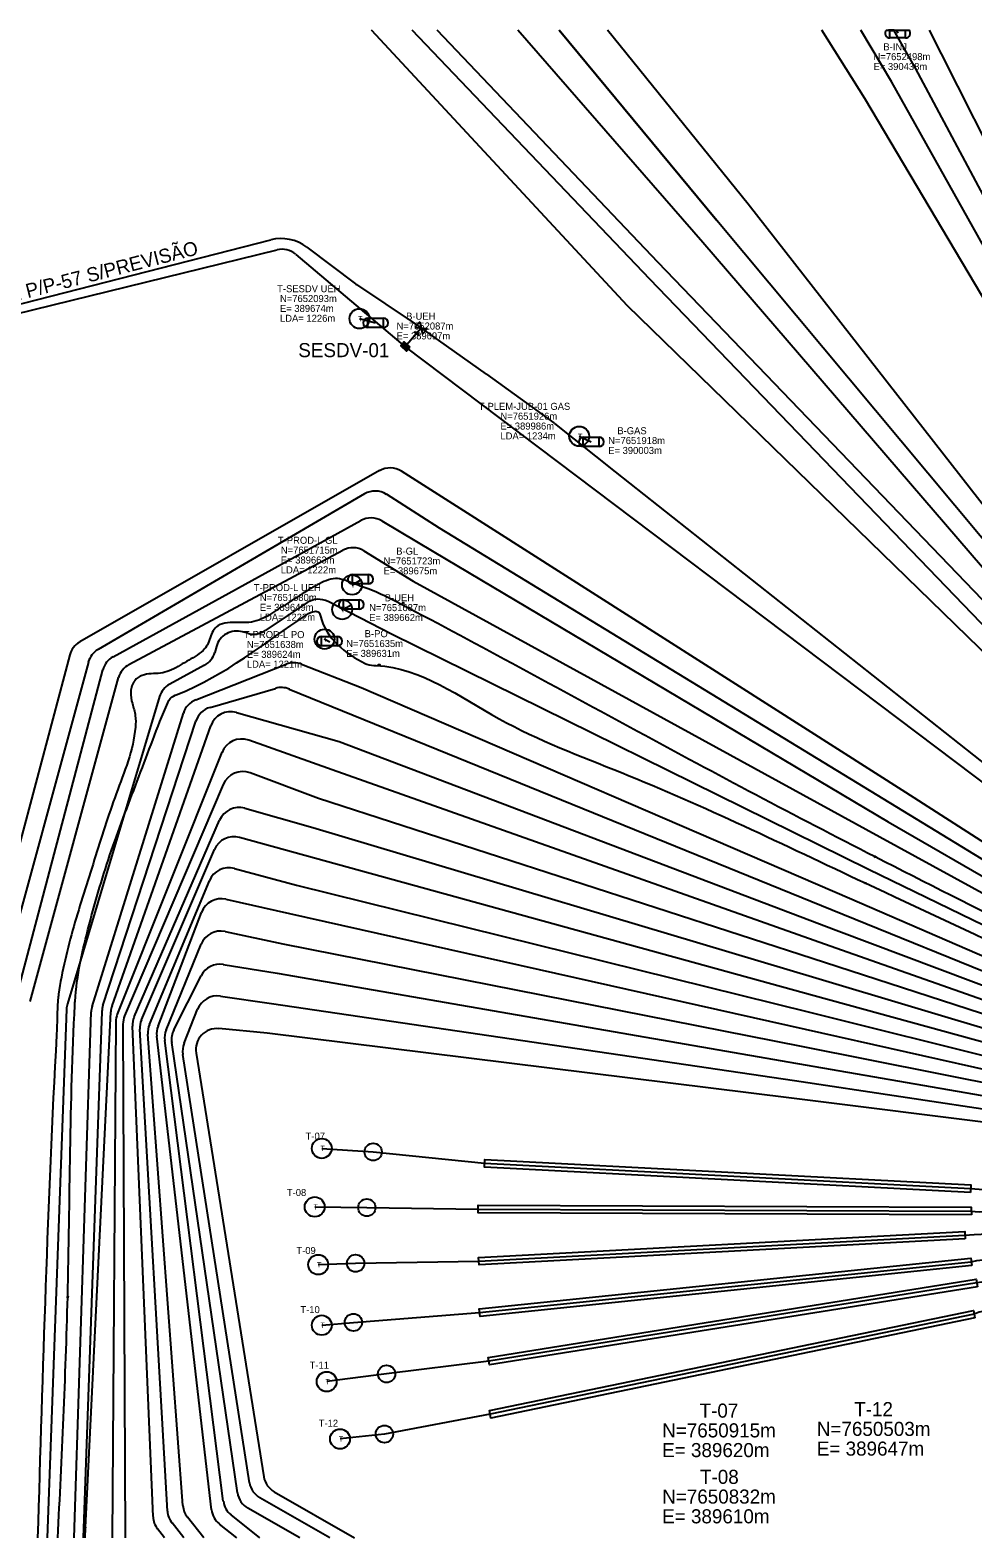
# Model space of a CAD drawing. Extents: x 387828 to 391861, y 7650362 to 7652502.
# Drawn here: x 389207 to 390545, y 7650362 to 7652502 of the extents above; entities that cross this region are included whole.
import ezdxf

# ---------------------------------------------------------------- set-up
doc = ezdxf.new("R2010")
doc.units = 0
for name, color, linetype in [('Blocos de producao br', 7, 'Continuous'), ('Coral', 7, 'Continuous'), ('Plataforma movel NS', 7, 'Continuous'), ('Sistemas de ancoragem', 7, 'Continuous'), ('TDP', 7, 'Continuous'), ('Textos dos campos', 7, 'Continuous'), ('Textos dos sistemas de ancoragem', 7, 'Continuous'), ('Variacoes de flexivel', 7, 'Continuous')]:
    doc.layers.add(name, color=color, linetype=linetype)

msp = doc.modelspace()

# ---------------------------------------------------------------- linework, layer by layer
at = {"layer": 'Blocos de producao br'}
for points in [[(389736.6, 7651688.6), (389735, 7651689.4), (389735.4, 7651690.2), (389737, 7651689.4)], [(389701.1, 7651602.5), (389702.9, 7651602.2), (389702.8, 7651601.3), (389701, 7651601.6)], [(390406.6, 7651328.2), (390405, 7651329), (390405.4, 7651329.8), (390407, 7651329)], [(390391.1, 7651292.8), (390392.8, 7651292), (390392.4, 7651291.2), (390390.8, 7651291.9)], [(389259.4, 7650703.1), (389259.5, 7650704.9), (389260.4, 7650704.9), (389260.3, 7650703)]]:
    msp.add_lwpolyline(points, close=True, dxfattribs=at)
at = {"layer": 'Plataforma movel NS'}
for points in [[(390838, 7651111), (390406, 7651329), (390236.7, 7651416.8), (390068.9, 7651507), (389901.1, 7651597.9), (389732, 7651688), (389686.6, 7651709.3), (389663.4, 7651717.7), (389640, 7651724), (389627, 7651721), (389601.8, 7651708.1), (389578.2, 7651693.1), (389554.9, 7651678), (389531, 7651665), (389517, 7651661.8), (389501.8, 7651661.8), (389486.7, 7651661.4), (389473, 7651657), (389466.3, 7651649.8), (389462.2, 7651640), (389458.2, 7651630), (389452, 7651622), (389428.6, 7651606.4), (389404, 7651593), (389391.7, 7651589.8), (389378.3, 7651588.9), (389365.6, 7651586.6), (389359.9, 7651583.7), (389355, 7651579), (389349.4, 7651563.3), (389351.7, 7651546.5), (389355.9, 7651529.5), (389356, 7651513), (389328.8, 7651418.6), (389297.7, 7651324.7), (389268.5, 7651230.2), (389247, 7651134), (389246, 7651126), (389245, 7651099), (389244, 7651076), (389217.2, 7650362.3)], [(389245.9, 7650362.3), (389259.9, 7650704), (389270, 7651118.4), (389270.3, 7651123.7), (389290.3, 7651232.4), (389322.1, 7651338.3), (389361, 7651442.8), (389401.9, 7651547.4), (389405.4, 7651553.7), (389415.3, 7651559.4), (389599.1, 7651672.6), (389610.3, 7651677.5), (389616.5, 7651676.1), (389618.8, 7651670.6), (389682, 7651603.6), (389684.6, 7651602.4), (389697.9, 7651600.5), (389872.2, 7651525.1), (390045.9, 7651448.6), (390391.8, 7651292), (390844.6, 7651082.5)]]:
    msp.add_spline(points, degree=3, dxfattribs=at)
at = {"layer": 'Sistemas de ancoragem'}
for p, q in [((390433.2, 7652502.5), (390424.8, 7652502.5)), ((390435.8, 7652502.5), (390438, 7652498)), ((389674, 7652093), (389697, 7652087)), ((389986, 7651926), (390003, 7651918)), ((389663.9, 7651714.8), (389676.2, 7651722.4)), ((389649.1, 7651679), (389662.2, 7651686.7)), ((389623.8, 7651638.6), (389632.2, 7651634.4))]:
    msp.add_line(p, q, dxfattribs=at)
for points in [[(389620.5, 7650915.1), (389693.5, 7650910.1), (389851.5, 7650894.1), (390541.5, 7650858.1), (390553.5, 7650857.1), (391048.5, 7650835.1), (391164.5, 7650832.6)], [(389610.5, 7650832.1), (389684.5, 7650831.1), (389842.5, 7650829.1), (390542.5, 7650826.1), (390553.5, 7650825.1), (391050.5, 7650827.1), (391164, 7650829.8)], [(389615.5, 7650750.1), (389668.5, 7650752.1), (389843.5, 7650755.1), (390533.5, 7650792.1), (390546.5, 7650793.1), (391044.5, 7650817.1), (391163.4, 7650827)], [(389620.5, 7650664.1), (389665.5, 7650668.1), (389844.5, 7650682.1), (390542.5, 7650754.1), (390550.5, 7650756.1), (391045.5, 7650809.1), (391162.9, 7650824.3)], [(391162.4, 7650821.5), (391054.5, 7650799.1), (390557.5, 7650725.1), (390550.5, 7650724.1), (389857.5, 7650613.1), (389712.5, 7650595.1), (389627.5, 7650584.1)], [(391157.8, 7650817.3), (391046.5, 7650788.7), (390553.5, 7650682.7), (390546.5, 7650679.7), (389859.5, 7650537.7), (389709.5, 7650509.7), (389646.5, 7650502.7)]]:
    msp.add_lwpolyline(points, dxfattribs=at)
for points in [[(390541.3, 7650852.7), (389851.3, 7650888.7), (389851.8, 7650899.5), (390541.8, 7650863.5)], [(390542.6, 7650820.7), (389842.6, 7650823.7), (389842.5, 7650834.5), (390542.5, 7650831.5)], [(390533.9, 7650786.7), (389843.9, 7650749.7), (389843.2, 7650760.4), (390533.2, 7650797.4)], [(390543.2, 7650748.7), (389845.2, 7650676.7), (389843.9, 7650687.4), (390541.9, 7650759.4)], [(390551.5, 7650718.8), (389858.5, 7650607.8), (389856.6, 7650618.4), (390549.6, 7650729.4)], [(390547.7, 7650674.4), (389860.7, 7650532.4), (389858.4, 7650542.9), (390545.4, 7650684.9)]]:
    msp.add_lwpolyline(points, close=True, dxfattribs=at)
for centre in [(389674, 7652093), (389986, 7651926), (389663.5, 7651715.1), (389649.5, 7651680.1), (389624.5, 7651638.1), (389620.5, 7650915.1), (389610.5, 7650832.1), (389615.5, 7650750.1), (389620.5, 7650664.1), (389627.5, 7650584.1), (389646.5, 7650502.7)]:
    msp.add_circle(centre, 14.1, dxfattribs=at)
msp.add_arc((390429, 7652516), 14.1, 252.6797, 287.3203, dxfattribs=at)
at = {"layer": 'TDP'}
for centre in [(389693.5, 7650910.1), (389684.5, 7650831.1), (389668.5, 7650752.1), (389665.5, 7650668.1), (389712.5, 7650595.1), (389709.5, 7650509.7)]:
    msp.add_circle(centre, 12.3, dxfattribs=at)
at = {"layer": 'Textos dos campos'}
for p, q in [((390421.9, 7652502.5), (390454.1, 7652502.5)), ((390426.8, 7652491.4), (390426.8, 7652502.5)), ((390449.3, 7652491.4), (390449.3, 7652502.5)), ((390449.3, 7652491.4), (390426.8, 7652491.4)), ((389685.8, 7652080.4), (389685.8, 7652093.6)), ((389708.3, 7652080.4), (389708.3, 7652093.6)), ((389708.3, 7652080.4), (389685.8, 7652080.4)), ((389991.8, 7651911.4), (389991.8, 7651924.6)), ((390014.3, 7651911.4), (390014.3, 7651924.6)), ((390014.3, 7651911.4), (389991.8, 7651911.4)), ((389664.3, 7651716.5), (389664.3, 7651729.7)), ((389686.8, 7651716.5), (389686.8, 7651729.7)), ((389686.8, 7651716.5), (389664.3, 7651716.5)), ((389651.3, 7651680.5), (389651.3, 7651693.7)), ((389673.8, 7651680.5), (389651.3, 7651680.5)), ((389673.8, 7651680.5), (389673.8, 7651693.7)), ((389620.3, 7651628.5), (389620.3, 7651641.7)), ((389642.8, 7651628.5), (389642.8, 7651641.7)), ((389642.8, 7651628.5), (389620.3, 7651628.5))]:
    msp.add_line(p, q, dxfattribs=at)
for points in [[(389685.8, 7652093.6), (389697, 7652093.6), (389708.3, 7652093.6)], [(389991.8, 7651924.6), (390003, 7651924.6), (390014.3, 7651924.6)], [(389664.3, 7651729.7), (389675.6, 7651729.7), (389686.8, 7651729.7)], [(389651.3, 7651693.7), (389662.6, 7651693.7), (389673.8, 7651693.7)], [(389620.3, 7651641.7), (389631.6, 7651641.7), (389642.8, 7651641.7)]]:
    msp.add_lwpolyline(points, dxfattribs=at)
for centre, radius, start, end in [((390426.8, 7652498), 6.6, 137.0647, 270.0255), ((390449.3, 7652498), 6.59, 270.0255, 43.0162), ((389685.8, 7652087), 6.6, 90, 270), ((389708.3, 7652087), 6.59, 270, 90), ((389991.8, 7651918), 6.6, 90, 270), ((390014.3, 7651918), 6.59, 270, 90), ((389664.3, 7651723.1), 6.6, 90, 270), ((389686.8, 7651723.1), 6.59, 270, 90), ((389651.3, 7651687.1), 6.6, 90, 270), ((389673.8, 7651687.1), 6.59, 270, 90), ((389620.3, 7651635.1), 6.6, 90, 270), ((389642.8, 7651635.1), 6.59, 270, 90)]:
    msp.add_arc(centre, radius, start, end, dxfattribs=at)
at = {"layer": 'Variacoes de flexivel'}
for p, q in [((390054.5, 7652111.3), (389691.1, 7652502.5)), ((390086.3, 7652149), (389748.7, 7652502.5)), ((390097.8, 7652172.9), (389784.4, 7652502.5)), ((390161.5, 7652201.2), (389898.7, 7652502.5)), ((389957.3, 7652502.5), (390181.2, 7652232.1)), ((390181.2, 7652232.1), (389957.3, 7652502.5)), ((390225.9, 7652255.7), (390026, 7652502.5)), ((390391.5, 7652405.6), (390330.2, 7652502.5)), ((390429.8, 7652428.9), (390385.7, 7652502.5)), ((390463.2, 7652448.4), (390432.6, 7652502.5)), ((390500.1, 7652468.8), (390483.1, 7652502.5)), ((390842.7, 7651790.4), (390500.1, 7652468.8)), ((390800.4, 7651765.4), (390429.8, 7652428.9)), ((390821.2, 7651778), (390463.2, 7652448.4)), ((390779, 7651751.8), (390391.5, 7652405.6)), ((390681.5, 7651671.6), (390225.9, 7652255.7)), ((390662.1, 7651656.5), (390181.2, 7652232.1)), ((388291.9, 7651884.1), (389548.2, 7652204.7)), ((389599.2, 7652194.5), (389668.2, 7652142.3)), ((390643.1, 7651641), (390161.5, 7652201.2)), ((388291.8, 7651879.6), (389557, 7652190.5)), ((389583.6, 7652184.2), (389738.7, 7652052.9)), ((390624.5, 7651625), (390097.8, 7652172.9)), ((389669.7, 7652141.3), (389751.9, 7652086.4)), ((390606.3, 7651608.6), (390086.3, 7652149)), ((390588.7, 7651591.7), (390054.5, 7652111.3)), ((389751.9, 7652086.4), (389853.9, 7652014.2)), ((389759.5, 7652088.4), (389752.5, 7652080.4)), ((389759.5, 7652088.4), (389763.5, 7652070.8)), ((389754.6, 7652071.5), (389738.9, 7652052.9)), ((389752.5, 7652080.4), (389770.5, 7652078.8)), ((389761.5, 7652079.6), (389755.7, 7652072.6)), ((389763.5, 7652070.8), (389770.5, 7652078.8)), ((389732.7, 7652054.4), (389735.1, 7652054.5)), ((389737.7, 7652059.9), (389737.8, 7652057.4)), ((389738.7, 7652052.9), (390572.9, 7651423.5)), ((389740.9, 7652049.3), (389741, 7652046.9)), ((389743.6, 7652052.2), (389746, 7652052.3)), ((389854.2, 7652014), (389950, 7651944.9)), ((389951.1, 7651944), (390037.2, 7651875.5)), ((389702.6, 7651877.2), (389276.9, 7651634)), ((389816.8, 7651823.5), (389733.6, 7651876.4)), ((390037.2, 7651875.5), (390586.1, 7651441.1)), ((389681.1, 7651844.2), (389303, 7651623.3)), ((389787.8, 7651795.4), (389712.4, 7651843.6)), ((390449.5, 7651420.4), (389816.8, 7651823.5)), ((389324.3, 7651613.1), (389676, 7651806.4)), ((389705.8, 7651805.9), (389779.7, 7651762)), ((390436.7, 7651399.7), (389787.8, 7651795.4)), ((389346.8, 7651602), (389650.5, 7651764.2)), ((389680.4, 7651763.3), (389750.3, 7651720.2)), ((389779.7, 7651762), (390424.4, 7651378.8)), ((389750.3, 7651720.2), (390412.5, 7651357.6)), ((389599.2, 7651689.6), (389540.1, 7651650.3)), ((389719.6, 7651645), (389629.6, 7651691.3)), ((389515.4, 7651646.3), (389508, 7651648.4)), ((390396.8, 7651311.1), (389719.6, 7651645)), ((389262.8, 7651615.6), (388929.3, 7650362.3)), ((389471, 7651627.6), (389468.7, 7651619.2)), ((389289.2, 7651605.3), (388950.3, 7650362.3)), ((389187, 7651130.1), (389309.8, 7651594.4)), ((389454.1, 7651600.9), (389404.7, 7651574.1)), ((389441.8, 7651551.9), (389570, 7651602.5)), ((389592, 7651602.6), (389676.3, 7651569.6)), ((389206.6, 7651123.8), (389332, 7651583.4)), ((389390.3, 7651556.4), (389259.5, 7651120.4)), ((389461.9, 7651541.1), (389554.8, 7651568.2)), ((389574.5, 7651567.2), (389665.2, 7651530.3)), ((389676.3, 7651569.6), (390369.4, 7651270.2)), ((389294.7, 7651116.8), (389424.2, 7651532.9)), ((389499.3, 7651533.9), (389645, 7651492.9)), ((389665.2, 7651530.3), (390360, 7651247.7)), ((389310, 7651117.9), (389441.8, 7651521.6)), ((389322.8, 7651117.6), (389462.9, 7651515)), ((389635.3, 7651452.5), (389516.8, 7651494.5)), ((389645, 7651492.9), (390350.9, 7651225.1)), ((389478.9, 7651477.4), (389330.3, 7651105.9)), ((389616, 7651412), (389518.7, 7651448.1)), ((390342.3, 7651202.2), (389635.3, 7651452.5)), ((389480.7, 7651431.7), (389340.7, 7651103.4)), ((390334.2, 7651179), (389616, 7651412)), ((391263.3, 7650896.9), (390449.5, 7651420.4)), ((389354.2, 7651101.7), (389475.6, 7651381)), ((389511.2, 7651397.9), (389608, 7651370.7)), ((391262.4, 7650895.3), (390436.7, 7651399.7)), ((389608, 7651370.7), (390326.5, 7651155.7)), ((390424.4, 7651378.8), (391261.6, 7650893.7)), ((389364.7, 7651097.8), (389468.3, 7651339.6)), ((389503.8, 7651356.7), (389596.3, 7651331.2)), ((390412.5, 7651357.6), (391260.8, 7650892.1)), ((389596.3, 7651331.2), (390319.4, 7651132.1)), ((389375.9, 7651091), (389461.1, 7651295)), ((389496.6, 7651312.4), (389584.8, 7651288.6)), ((391259.9, 7650890.5), (390396.8, 7651311.1)), ((389584.8, 7651288.6), (390312.8, 7651108.3)), ((389484.6, 7651268.7), (389574.8, 7651248.5)), ((390369.4, 7651270.2), (391257.4, 7650885.7)), ((389388.1, 7651088.6), (389450, 7651250.2)), ((389574.8, 7651248.5), (390306.6, 7651084.4)), ((390360, 7651247.7), (391256.5, 7650884.1)), ((389483.3, 7651223.1), (389565.3, 7651205.5)), ((390350.9, 7651225.1), (391255.7, 7650882.5)), ((389399.6, 7651083.2), (389449.2, 7651205)), ((389565.3, 7651205.5), (390301, 7651060.2)), ((391254.8, 7650880.9), (390342.3, 7651202.2)), ((389480.8, 7651176.4), (389557, 7651164.1)), ((391253.9, 7650879.3), (390334.2, 7651179)), ((389410.5, 7651083.3), (389449.3, 7651160.2)), ((389557, 7651164.1), (390296, 7651035.8)), ((390326.5, 7651155.7), (391253.1, 7650877.7)), ((389476.6, 7651131.3), (389549.4, 7651120.6)), ((390319.4, 7651132.1), (391252.3, 7650876.1)), ((389269.2, 7650362.3), (389293.3, 7651108.8)), ((389282.3, 7650362.3), (389308.6, 7651109.6)), ((389285.3, 7650377.2), (389321.1, 7651109.1)), ((389425.1, 7651064.3), (389444.3, 7651112.7)), ((389549.4, 7651120.6), (390291.4, 7651011.3)), ((390312.8, 7651108.3), (391251.4, 7650874.5)), ((389328.2, 7651095), (389322.8, 7650362.3)), ((389338.3, 7651091.5), (389341.6, 7650362.3)), ((389381, 7650392.4), (389351.7, 7651088.5)), ((389401.6, 7650400.3), (389362.3, 7651084.3)), ((389543.1, 7651078.8), (389474.4, 7651085.1)), ((390306.6, 7651084.4), (391250.6, 7650872.9)), ((389423.3, 7650408.1), (389373.7, 7651077.2)), ((389464.1, 7650402), (389386.3, 7651074.4)), ((389480.8, 7650414.6), (389397.6, 7651068.1)), ((389501, 7650426), (389407.6, 7651065.5)), ((390287.4, 7650986.5), (389543.1, 7651078.8)), ((390301, 7651060.2), (391249.7, 7650871.3)), ((389518, 7650440.6), (389423.3, 7651048.6)), ((389442.1, 7651050.4), (389538.3, 7650449.1)), ((390296, 7651035.8), (391248.9, 7650869.8)), ((390291.4, 7651011.3), (391248, 7650868.2)), ((391247.2, 7650866.5), (390287.4, 7650986.5)), ((389632.1, 7650362.3), (389532.7, 7650419.2)), ((389553, 7650427.8), (389667, 7650362.3)), ((389532.7, 7650362.3), (389491.8, 7650394.9)), ((389589.3, 7650362.3), (389515.8, 7650404.3)), ((389284.8, 7650362.3), (389285.2, 7650376.7)), ((389397.4, 7650362.3), (389387.4, 7650375.1)), ((389424.7, 7650362.3), (389408, 7650383.4)), ((389453.1, 7650362.3), (389429.8, 7650391.6)), ((389500.1, 7650362.3), (389475.3, 7650381.9))]:
    msp.add_line(p, q, dxfattribs=at)
for points in [[(389753, 7652074.9), (389758.4, 7652070.3), (389757.5, 7652069.2), (389752, 7652073.8)], [(389746, 7652052.3), (389737.7, 7652059.9), (389732.7, 7652054.4), (389741, 7652046.9)], [(389743.6, 7652052.2), (389737.8, 7652057.4), (389735.1, 7652054.5), (389740.9, 7652049.3)]]:
    msp.add_lwpolyline(points, close=True, dxfattribs=at)
msp.add_lwpolyline([(389258.2, 7651112.9), (389230.6, 7650362.3)], dxfattribs=at)
for centre, radius, start, end in [((389563, 7652146.6), 60, 52.9303, 104.3183), ((389564.2, 7652161.4), 30, 49.7436, 103.8037), ((389686.3, 7652166.2), 30, 232.9303, 236.2803), ((389836.6, 7651989.7), 30, 54.183, 54.7117), ((389932.4, 7651920.5), 30, 51.4597, 54.183), ((389717.5, 7651851.1), 30, 57.5025, 119.7371), ((389696.2, 7651818.3), 30, 57.465, 120.2923), ((389690.4, 7651780.1), 30, 59.2751, 118.8023), ((389664.7, 7651737.8), 30, 58.3166, 118.111), ((389615.8, 7651664.6), 30, 62.7809, 123.6471), ((389499.9, 7651619.5), 30, 74.4018, 164.4018), ((389523.5, 7651675.2), 30, 254.4018, 303.6471), ((389291.8, 7651607.9), 30, 119.7371, 165.1023), ((389318.1, 7651597.4), 30, 120.2923, 164.7508), ((389439.8, 7651627.2), 30, 298.4385, 344.4018), ((389338.8, 7651586.8), 30, 118.8023, 165.1912), ((389361, 7651575.5), 30, 118.111, 164.7379), ((389581, 7651574.6), 30, 68.6631, 111.5428), ((389419, 7651547.8), 30, 118.4385, 163.3004), ((389452.8, 7651524), 30, 111.5428, 162.7145), ((389563.2, 7651539.4), 30, 67.8648, 106.2579), ((389470.3, 7651512.3), 30, 106.2579, 161.9266), ((389491.2, 7651505), 30, 74.2651, 160.5813), ((389506.8, 7651466.2), 30, 70.4881, 158.1989), ((389508.3, 7651420), 30, 69.6581, 156.9077), ((389503.1, 7651369), 30, 74.3336, 156.5098), ((389495.8, 7651327.7), 30, 74.5986, 156.8022), ((389488.8, 7651283.5), 30, 74.8541, 157.336), ((389478, 7651239.5), 30, 77.3542, 159.0305), ((389477, 7651193.7), 30, 77.9229, 157.8338), ((389476.1, 7651146.7), 30, 80.8652, 153.2689), ((389472.2, 7651101.6), 30, 81.6289, 158.3207), ((389288.2, 7651111.8), 30, 163.3004, 177.8886), ((389323.3, 7651107.9), 30, 162.7145, 178.1509), ((389338.5, 7651108.6), 30, 161.9266, 177.9894), ((389351.1, 7651107.6), 30, 160.5813, 177.1959), ((389358.2, 7651094.7), 30, 158.1989, 179.5817), ((389368.3, 7651091.6), 30, 156.9077, 180.2569), ((389381.7, 7651089.7), 30, 156.5098, 182.4067), ((389392.2, 7651086), 30, 156.8022, 183.2883), ((389403.6, 7651079.5), 30, 157.336, 184.2447), ((389416.1, 7651077.9), 30, 159.0305, 186.6042), ((389427.4, 7651071.9), 30, 157.8338, 187.2551), ((389437.3, 7651069.8), 30, 153.2689, 188.303), ((389471.7, 7651055.2), 30, 84.7597, 189.094), ((389453, 7651053.2), 30, 158.3207, 188.8471), ((389547.6, 7650445.2), 30, 188.8471, 240.2219), ((389567.9, 7650453.8), 30, 189.094, 240.131), ((389530.6, 7650430.4), 30, 188.303, 240.2636), ((389431.5, 7650402), 30, 183.2883, 218.3784), ((389453.3, 7650410.3), 30, 184.2447, 218.5182), ((389493.9, 7650405.5), 30, 186.6042, 231.6484), ((389510.6, 7650418.4), 30, 187.2551, 231.3908), ((389315.2, 7650375.8), 30, 177.1959, 178.2334), ((389411, 7650393.6), 30, 182.4067, 218.153)]:
    msp.add_arc(centre, radius, start, end, dxfattribs=at)

# ---------------------------------------------------------------- texts
at = {"layer": 'Coral'}
msp.add_text('PROJETO DO GASOD.9.13"/UH DO PLEM-JUB-01 P/P-57 S/PREVISÃO', height=20, rotation=14.3587, dxfattribs=at).set_placement((388596.5, 7651966.8))
msp.add_text('SESDV-01', height=20, dxfattribs=at).set_placement((389587.2, 7652038.3))
at = {"layer": 'Sistemas de ancoragem'}
for p in [(389672.1, 7652089.2), (389984.1, 7651922.2), (389661.6, 7651711.3), (389647.6, 7651676.3), (389622.6, 7651634.3), (389618.6, 7650911.3), (389608.6, 7650828.3), (389613.6, 7650746.3), (389618.6, 7650660.3), (389625.6, 7650580.3), (389644.6, 7650498.9)]:
    msp.add_text('T', height=7.62, dxfattribs=at).set_placement(p)
at = {"layer": 'Textos dos sistemas de ancoragem'}
for s, height, p in [('B-INJ', 10, (390417.7, 7652473.9)), ('N=7652498m', 10, (390403.7, 7652459.9)), ('E= 390438m', 10, (390403.7, 7652445.9)), ('T-SESDV UEH', 10, (389557.2, 7652130.5)), ('N=7652093m', 10, (389561.2, 7652116.5)), ('E= 389674m', 10, (389561.2, 7652102.5)), ('LDA= 1226m', 10, (389561.2, 7652088.5)), ('N=7652087m', 10, (389726.7, 7652077.5)), ('B-UEH', 10, (389740.3, 7652091.5)), ('E= 389697m', 10, (389726.7, 7652063.5)), ('T-PLEM-JUB-01 GAS', 10, (389843.2, 7651963.5)), ('N=7651926m', 10, (389874.1, 7651949.5)), ('E= 389986m', 10, (389874.1, 7651935.5)), ('B-GAS', 10, (390040.1, 7651928.9)), ('LDA= 1234m', 10, (389874.1, 7651921.5)), ('N=7651918m', 10, (390027.1, 7651914.9)), ('E= 390003m', 10, (390027.1, 7651900.9)), ('T-PROD-L GL', 10, (389558.3, 7651773.4)), ('N=7651715m', 10, (389562.4, 7651759.4)), ('B-GL', 10, (389726.2, 7651758)), ('E= 389663m', 10, (389562.4, 7651745.4)), ('N=7651723m', 10, (389708.2, 7651744)), ('LDA= 1222m', 10, (389562.4, 7651731.4)), ('E= 389675m', 10, (389708.2, 7651730)), ('T-PROD-L UEH', 10, (389524.1, 7651706.2)), ('N=7651680m', 10, (389532.6, 7651692.2)), ('B-UEH', 10, (389710, 7651691.8)), ('E= 389649m', 10, (389532.6, 7651678.2)), ('N=7651687m', 10, (389687.8, 7651677.8)), ('LDA= 1222m', 10, (389532.6, 7651664.2)), ('E= 389662m', 10, (389687.8, 7651663.8)), ('T-PROD-L PO', 10, (389509.8, 7651639.5)), ('N=7651635m', 10, (389655.2, 7651626.8)), ('B-PO', 10, (389681.5, 7651640.8)), ('N=7651638m', 10, (389514.2, 7651625.5)), ('E= 389624m', 10, (389514.2, 7651611.5)), ('E= 389631m', 10, (389655.2, 7651612.8)), ('LDA= 1221m', 10, (389514.2, 7651597.5)), ('T-07', 10, (389597.6, 7650927.5)), ('T-08', 10, (389571, 7650847.5)), ('T-09', 10, (389584.5, 7650765.2)), ('T-10', 10, (389590.2, 7650681.3)), ('T-11', 10, (389603.3, 7650602.5)), ('T-07', 20, (390156.8, 7650532.9)), ('T-12', 20, (390376.3, 7650535)), ('T-12', 10, (389616.2, 7650520)), ('N=7650915m', 20, (390103.7, 7650504.9)), ('N=7650503m', 20, (390323.2, 7650507)), ('E= 389620m', 20, (390103.7, 7650476.9)), ('E= 389647m', 20, (390323.2, 7650479)), ('T-08', 20, (390157.4, 7650438.9)), ('N=7650832m', 20, (390103.7, 7650410.9)), ('E= 389610m', 20, (390103.7, 7650382.9))]:
    msp.add_text(s, height=height, dxfattribs=at).set_placement(p)

doc.saveas('drawing.dxf')
